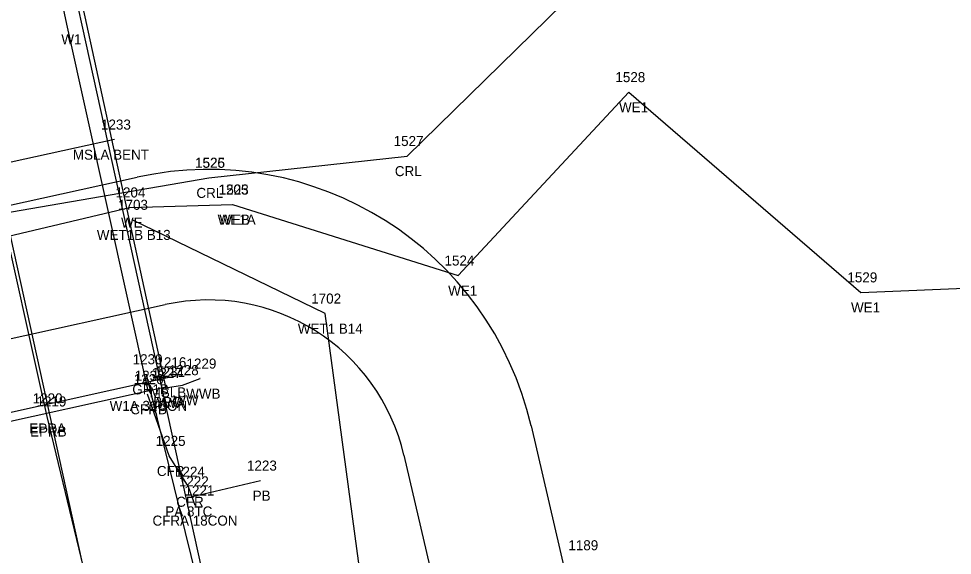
# Model space of a CAD drawing. Extents: x 2521558 to 2524785, y 882711 to 887632.
# Drawn here: x 2523806.5 to 2523899.5, y 885071.1 to 885124.5 of the extents above; entities that cross this region are included whole.
import ezdxf

# ---------------------------------------------------------------- set-up
doc = ezdxf.new("R2010")
doc.units = 0
for name, color, linetype in [('RD_EV_JW', 7, 'Continuous'), ('RD_EX_BldgApp', 7, 'Continuous'), ('RD_EX_BldgApp_txCode', 7, 'Continuous'), ('RD_EX_Bridge', 7, 'Continuous'), ('RD_EX_Bridge_txCode', 7, 'Continuous'), ('RD_EX_Conc', 7, 'Continuous'), ('RD_EX_Conc_txCode', 7, 'Continuous'), ('RD_EX_DR_Pipe', 7, 'Continuous'), ('RD_EX_DR_Pipe_txCode', 7, 'Continuous'), ('RD_EX_GuardRail', 7, 'Continuous'), ('RD_EX_GuardRail_txCode', 7, 'Continuous'), ('RD_EX_H2O', 7, 'Continuous'), ('RD_EX_H2O_txCode', 7, 'Continuous'), ('RD_EX_H2O_WetLd_txCode', 7, 'Continuous'), ('RD_EX_Misc', 7, 'Continuous'), ('RD_EX_Misc_txCode', 7, 'Continuous'), ('RD_EX_Road', 7, 'Continuous'), ('RD_EX_Road_txCode', 7, 'Continuous'), ('RD_EX_VEG_txCode', 7, 'Continuous'), ('RD_PD_Bridge', 7, 'Continuous'), ('RD_PD_CstnLmt', 7, 'Continuous'), ('RD_PD_DR_ErosCtrl', 7, 'Continuous'), ('RD_PD_Final_TrvlWay', 7, 'Continuous'), ('RD_SMD_Locator', 7, 'Continuous')]:
    doc.layers.add(name, color=color, linetype=linetype)

msp = doc.modelspace()

# ---------------------------------------------------------------- linework, layer by layer
at = {"layer": 'RD_EV_JW'}
msp.add_lwpolyline([(2523944.864, 884550.08), (2523910.413, 884709.577), (2523888.007, 884815.03), (2523863.93, 884918.366), (2523848.427, 885010.841), (2523837.066, 885095.132), (2523817.825, 885104.474)], dxfattribs=at)
at = {"layer": 'RD_EX_BldgApp'}
msp.add_lwpolyline([(2523819.439, 885087.441), (2523811.319, 885123.961), (2523803.308, 885161.503)], dxfattribs=at)
at = {"layer": 'RD_EX_Bridge'}
for points in [[(2523774.906, 885077.596), (2523821.197, 885087.829), (2523805.064, 885161.895), (2523758.145, 885151.437), (2523774.906, 885077.596)], [(2523821.146, 885087.728), (2523822.84, 885087.999), (2523824.599, 885088.655)]]:
    msp.add_lwpolyline(points, dxfattribs=at)
at = {"layer": 'RD_EX_Conc'}
msp.add_lwpolyline([(2523824.118, 885076.01), (2523823.453, 885077.886), (2523821.532, 885080.953), (2523819.362, 885087.102)], dxfattribs=at)
at = {"layer": 'RD_EX_DR_Pipe'}
msp.add_line((2523823.84, 885076.923), (2523830.626, 885078.493), dxfattribs=at)
at = {"layer": 'RD_EX_GuardRail'}
msp.add_lwpolyline([(2523841.112, 885013.814), (2523827.604, 885055.265), (2523819.275, 885089.086)], dxfattribs=at)
at = {"layer": 'RD_EX_H2O'}
for points in [[(2523582.816, 884766.342), (2523598.112, 884856.984), (2523627.586, 884901.753), (2523623.762, 884928.278), (2523586.58, 884955.428), (2523600.942, 884974.118), (2523633.055, 884997.681), (2523679.166, 885037.048), (2523744.717, 885076.895), (2523769.376, 885098.995), (2523825.47, 885108.66), (2523825.47, 885108.66), (2523845.237, 885110.828), (2523890.252, 885154.934), (2523858.435, 885178.041), (2523850.814, 885196.928), (2523892.509, 885249.744), (2523936.89, 885290.086), (2523980.857, 885285.467), (2524009.058, 885269.77), (2524037.386, 885280.087)], [(2523827.825, 885105.996), (2523850.303, 885098.921), (2523867.326, 885117.194), (2523890.438, 885097.244), (2523927.793, 885098.781), (2523966.352, 885109.501), (2523978.174, 885083.367)], [(2523792.732, 884941.121), (2523763.674, 885051.555), (2523756.264, 885062.719), (2523770.471, 885094.548), (2523817.567, 885105.706), (2523827.825, 885105.996)]]:
    msp.add_lwpolyline(points, dxfattribs=at)
at = {"layer": 'RD_EX_Misc'}
for p, q in [((2523816.084, 885112.468), (2523769.205, 885102.217)), ((2523774.429, 885078.307), (2523821.346, 885088.784))]:
    msp.add_line(p, q, dxfattribs=at)
at = {"layer": 'RD_EX_Road'}
for p, q in [((2523809.315, 885085.19), (2523803.791, 885109.941)), ((2523809.375, 885084.881), (2523809.315, 885085.19)), ((2523817.578, 885050.917), (2523809.375, 885084.881))]:
    msp.add_line(p, q, dxfattribs=at)
at = {"layer": 'RD_PD_Bridge'}
msp.add_lwpolyline([(2523826.629, 885061.235), (2523798.673, 885188.194)], dxfattribs=at)
at = {"layer": 'RD_PD_CstnLmt'}
msp.add_line((2523844.918, 885081.017), (2523855.75, 885034.367), dxfattribs=at)
msp.add_lwpolyline([(2523770.593, 885084.896), (2523821.135, 885096.025)], dxfattribs=at)
msp.add_arc((2523825.436, 885076.493), 20, 13.07237, 102.41848, dxfattribs=at)
at = {"layer": 'RD_PD_DR_ErosCtrl'}
msp.add_line((2523857.581, 885083.957), (2523868.413, 885037.307), dxfattribs=at)
msp.add_lwpolyline([(2523767.797, 885097.592), (2523818.34, 885108.721)], dxfattribs=at)
msp.add_arc((2523825.436, 885076.493), 33, 13.07237, 102.41848, dxfattribs=at)
at = {"layer": 'RD_PD_Final_TrvlWay'}
msp.add_line((2523741.744, 885393.246), (2524015.933, 884148.078), dxfattribs=at)
at = {"layer": 'RD_SMD_Locator'}
for centre in [(2523811.319, 885123.961), (2523867.326, 885117.194), (2523816.084, 885112.468), (2523845.237, 885110.828), (2523825.47, 885108.66), (2523825.47, 885108.66), (2523827.825, 885105.996), (2523827.825, 885105.996), (2523817.567, 885105.706), (2523817.825, 885104.474), (2523850.303, 885098.921), (2523890.438, 885097.244), (2523837.066, 885095.132), (2523819.275, 885089.086), (2523821.346, 885088.784), (2523824.599, 885088.655), (2523819.439, 885087.441), (2523821.146, 885087.728), (2523821.197, 885087.829), (2523822.84, 885087.999), (2523819.362, 885087.102), (2523809.315, 885085.19), (2523809.375, 885084.881), (2523821.532, 885080.953), (2523823.453, 885077.886), (2523830.626, 885078.493), (2523823.84, 885076.923), (2523824.118, 885076.01)]:
    msp.add_circle(centre, 0.001, dxfattribs=at)

# ---------------------------------------------------------------- texts
at = {"layer": 'RD_EX_BldgApp_txCode'}
for s, p in [('W1', (2523810.784, 885121.961)), ('1232', (2523818.093, 885088.441)), ('W1A 32CON', (2523815.597, 885085.441))]:
    msp.add_text(s, height=1, dxfattribs=at).set_placement(p)
at = {"layer": 'RD_EX_Bridge_txCode'}
for s, p in [('1228', (2523821.494, 885088.999)), ('1229', (2523823.253, 885089.655)), ('1227', (2523819.799, 885088.728)), ('1231', (2523820.134, 885088.829)), ('WWB', (2523823.221, 885086.655)), ('WWA', (2523819.752, 885085.728)), ('BRC', (2523819.945, 885085.829)), ('WW', (2523821.934, 885085.999))]:
    msp.add_text(s, height=1, dxfattribs=at).set_placement(p)
at = {"layer": 'RD_EX_Conc_txCode'}
for s, p in [('1226', (2523817.992, 885088.102)), ('CFRB', (2523817.661, 885085.102)), ('1225', (2523820.185, 885081.953)), ('CFR', (2523820.303, 885078.953)), ('1224', (2523822.107, 885078.886)), ('1221', (2523823.055, 885077.01)), ('CFR', (2523822.225, 885075.886)), ('CFRA 18CON', (2523819.866, 885074.01))]:
    msp.add_text(s, height=1, dxfattribs=at).set_placement(p)
at = {"layer": 'RD_EX_DR_Pipe_txCode'}
for s, p in [('1223', (2523829.28, 885079.493)), ('1222', (2523822.493, 885077.923)), ('PB', (2523829.846, 885076.493)), ('PA 8TC', (2523821.147, 885074.923))]:
    msp.add_text(s, height=1, dxfattribs=at).set_placement(p)
at = {"layer": 'RD_EX_GuardRail_txCode'}
for s, p in [('1230', (2523817.89, 885090.086)), ('GR1B', (2523817.858, 885087.086))]:
    msp.add_text(s, height=1, dxfattribs=at).set_placement(p)
at = {"layer": 'RD_EX_H2O_txCode'}
for s, p in [('1528', (2523865.98, 885118.194)), ('WE1', (2523866.342, 885115.194)), ('1527', (2523843.89, 885111.828)), ('1526', (2523824.1, 885109.66)), ('1525', (2523824.124, 885109.66)), ('CRL', (2523844.008, 885108.828)), ('1204', (2523816.181, 885106.706)), ('CRL', (2523824.242, 885106.66)), ('CRL', (2523824.242, 885106.66)), ('1205', (2523826.44, 885106.996)), ('1523', (2523826.479, 885106.996)), ('WE1A', (2523826.353, 885103.996)), ('WEB', (2523826.534, 885103.996)), ('WE', (2523816.729, 885103.706)), ('1524', (2523848.957, 885099.921)), ('1529', (2523889.091, 885098.244)), ('WE1', (2523849.319, 885096.921)), ('WE1', (2523889.453, 885095.244))]:
    msp.add_text(s, height=1, dxfattribs=at).set_placement(p)
at = {"layer": 'RD_EX_H2O_WetLd_txCode'}
for s, p in [('1703', (2523816.439, 885105.474)), ('WET1B B13', (2523814.321, 885102.474)), ('1702', (2523835.68, 885096.132)), ('WET1 B14', (2523834.341, 885093.132))]:
    msp.add_text(s, height=1, dxfattribs=at).set_placement(p)
at = {"layer": 'RD_EX_Misc_txCode'}
for s, p in [('1233', (2523814.737, 885113.468)), ('MSLA BENT', (2523811.934, 885110.468)), ('1216', (2523820.259, 885089.784)), ('MSLB', (2523819.582, 885086.784))]:
    msp.add_text(s, height=1, dxfattribs=at).set_placement(p)
at = {"layer": 'RD_EX_Road_txCode'}
for s, p in [('1220', (2523807.93, 885086.19)), ('1219', (2523808.312, 885085.881)), ('EPRA', (2523807.599, 885083.19)), ('EPRB', (2523807.675, 885082.881))]:
    msp.add_text(s, height=1, dxfattribs=at).set_placement(p)
at = {"layer": 'RD_EX_VEG_txCode'}
msp.add_text('1189', height=1, dxfattribs=at).set_placement((2523861.294, 885071.557))

doc.saveas('drawing.dxf')
